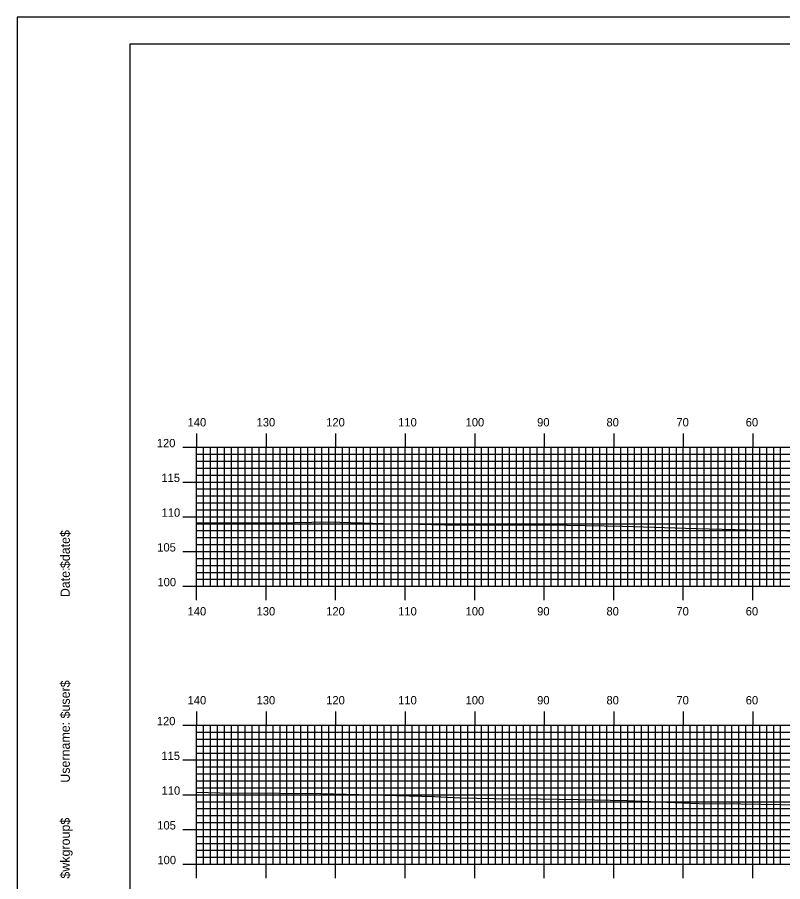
# Model space of a CAD drawing. Extents: x 1773203 to 1773546, y 442591 to 442811.
# Drawn here: x 1773202.8 to 1773312.9, y 442686.2 to 442810.5 of the extents above; entities that cross this region are included whole.
import ezdxf

# ---------------------------------------------------------------- set-up
doc = ezdxf.new("R2010")
doc.units = 0
for name, color, linetype in [('BORDER', 7, 'Continuous'), ('H_V ANNOTATION', 7, 'Continuous'), ('MAJOR', 7, 'Continuous'), ('MINOR', 7, 'Continuous'), ('PLOT BOUNDARY', 7, 'Continuous'), ('S_Roadway_Centerline', 7, 'Continuous')]:
    doc.layers.add(name, color=color, linetype=linetype)

msp = doc.modelspace()

# ---------------------------------------------------------------- linework, layer by layer
at = {"layer": 'BORDER'}
msp.add_lwpolyline([(1773219.03, 442596.67), (1773539.03, 442596.67), (1773539.03, 442806.67), (1773219.03, 442806.67)], close=True, dxfattribs=at)
at = {"layer": 'MAJOR'}
for p, q in [((1773228.63, 442750.67), (1773228.63, 442748.67)), ((1773238.63, 442750.67), (1773238.63, 442748.67)), ((1773248.63, 442750.67), (1773248.63, 442748.67)), ((1773258.63, 442750.67), (1773258.63, 442748.67)), ((1773268.63, 442750.67), (1773268.63, 442748.67)), ((1773278.63, 442750.67), (1773278.63, 442748.67)), ((1773288.63, 442750.67), (1773288.63, 442748.67)), ((1773298.63, 442750.67), (1773298.63, 442748.67)), ((1773308.63, 442750.67), (1773308.63, 442748.67)), ((1773226.63, 442748.67), (1773228.63, 442748.67)), ((1773228.63, 442748.67), (1773508.63, 442748.67)), ((1773228.63, 442728.67), (1773228.63, 442748.67)), ((1773228.63, 442728.67), (1773228.63, 442748.67)), ((1773228.63, 442748.67), (1773508.63, 442748.67)), ((1773238.63, 442728.67), (1773238.63, 442748.67)), ((1773248.63, 442728.67), (1773248.63, 442748.67)), ((1773258.63, 442728.67), (1773258.63, 442748.67)), ((1773268.63, 442728.67), (1773268.63, 442748.67)), ((1773278.63, 442728.67), (1773278.63, 442748.67)), ((1773288.63, 442728.67), (1773288.63, 442748.67)), ((1773298.63, 442728.67), (1773298.63, 442748.67)), ((1773308.63, 442728.67), (1773308.63, 442748.67)), ((1773226.63, 442743.67), (1773228.63, 442743.67)), ((1773228.63, 442743.67), (1773508.63, 442743.67)), ((1773226.63, 442738.67), (1773228.63, 442738.67)), ((1773228.63, 442738.67), (1773508.63, 442738.67)), ((1773226.63, 442733.67), (1773228.63, 442733.67)), ((1773228.63, 442733.67), (1773508.63, 442733.67)), ((1773226.63, 442728.67), (1773228.63, 442728.67)), ((1773228.63, 442728.67), (1773508.63, 442728.67)), ((1773228.63, 442728.67), (1773508.63, 442728.67)), ((1773228.63, 442726.66), (1773228.63, 442728.67)), ((1773238.63, 442726.66), (1773238.63, 442728.67)), ((1773248.63, 442726.66), (1773248.63, 442728.67)), ((1773258.63, 442726.66), (1773258.63, 442728.67)), ((1773268.63, 442726.66), (1773268.63, 442728.67)), ((1773278.63, 442726.66), (1773278.63, 442728.67)), ((1773288.63, 442726.66), (1773288.63, 442728.67)), ((1773298.63, 442726.66), (1773298.63, 442728.67)), ((1773308.63, 442726.66), (1773308.63, 442728.67)), ((1773228.63, 442710.67), (1773228.63, 442708.67)), ((1773238.63, 442710.67), (1773238.63, 442708.67)), ((1773248.63, 442710.67), (1773248.63, 442708.67)), ((1773258.63, 442710.67), (1773258.63, 442708.67)), ((1773268.63, 442710.67), (1773268.63, 442708.67)), ((1773278.63, 442710.67), (1773278.63, 442708.67)), ((1773288.63, 442710.67), (1773288.63, 442708.67)), ((1773298.63, 442710.67), (1773298.63, 442708.67)), ((1773308.63, 442710.67), (1773308.63, 442708.67)), ((1773226.63, 442708.67), (1773228.63, 442708.67)), ((1773228.63, 442708.67), (1773508.63, 442708.67)), ((1773228.63, 442688.67), (1773228.63, 442708.67)), ((1773228.63, 442688.67), (1773228.63, 442708.67)), ((1773228.63, 442708.67), (1773508.63, 442708.67)), ((1773238.63, 442688.67), (1773238.63, 442708.67)), ((1773248.63, 442688.67), (1773248.63, 442708.67)), ((1773258.63, 442688.67), (1773258.63, 442708.67)), ((1773268.63, 442688.67), (1773268.63, 442708.67)), ((1773278.63, 442688.67), (1773278.63, 442708.67)), ((1773288.63, 442688.67), (1773288.63, 442708.67)), ((1773298.63, 442688.67), (1773298.63, 442708.67)), ((1773308.63, 442688.67), (1773308.63, 442708.67)), ((1773226.63, 442703.67), (1773228.63, 442703.67)), ((1773228.63, 442703.67), (1773508.63, 442703.67)), ((1773226.63, 442698.67), (1773228.63, 442698.67)), ((1773228.63, 442698.67), (1773508.63, 442698.67)), ((1773226.63, 442693.67), (1773228.63, 442693.67)), ((1773228.63, 442693.67), (1773508.63, 442693.67)), ((1773226.63, 442688.67), (1773228.63, 442688.67)), ((1773228.63, 442688.67), (1773508.63, 442688.67)), ((1773228.63, 442688.67), (1773508.63, 442688.67)), ((1773228.63, 442686.66), (1773228.63, 442688.67)), ((1773238.63, 442686.66), (1773238.63, 442688.67)), ((1773248.63, 442686.66), (1773248.63, 442688.67)), ((1773258.63, 442686.66), (1773258.63, 442688.67)), ((1773268.63, 442686.66), (1773268.63, 442688.67)), ((1773278.63, 442686.66), (1773278.63, 442688.67)), ((1773288.63, 442686.66), (1773288.63, 442688.67)), ((1773298.63, 442686.66), (1773298.63, 442688.67)), ((1773308.63, 442686.66), (1773308.63, 442688.67))]:
    msp.add_line(p, q, dxfattribs=at)
at = {"layer": 'MINOR'}
for p, q in [((1773229.63, 442728.67), (1773229.63, 442748.67)), ((1773230.63, 442728.67), (1773230.63, 442748.67)), ((1773231.63, 442728.67), (1773231.63, 442748.67)), ((1773232.63, 442728.67), (1773232.63, 442748.67)), ((1773233.63, 442728.67), (1773233.63, 442748.67)), ((1773234.63, 442728.67), (1773234.63, 442748.67)), ((1773235.63, 442728.67), (1773235.63, 442748.67)), ((1773236.63, 442728.67), (1773236.63, 442748.67)), ((1773237.63, 442728.67), (1773237.63, 442748.67)), ((1773239.63, 442728.67), (1773239.63, 442748.67)), ((1773240.63, 442728.67), (1773240.63, 442748.67)), ((1773241.63, 442728.67), (1773241.63, 442748.67)), ((1773242.63, 442728.67), (1773242.63, 442748.67)), ((1773243.63, 442728.67), (1773243.63, 442748.67)), ((1773244.63, 442728.67), (1773244.63, 442748.67)), ((1773245.63, 442728.67), (1773245.63, 442748.67)), ((1773246.63, 442728.67), (1773246.63, 442748.67)), ((1773247.63, 442728.67), (1773247.63, 442748.67)), ((1773249.63, 442728.67), (1773249.63, 442748.67)), ((1773250.63, 442728.67), (1773250.63, 442748.67)), ((1773251.63, 442728.67), (1773251.63, 442748.67)), ((1773252.63, 442728.67), (1773252.63, 442748.67)), ((1773253.63, 442728.67), (1773253.63, 442748.67)), ((1773254.63, 442728.67), (1773254.63, 442748.67)), ((1773255.63, 442728.67), (1773255.63, 442748.67)), ((1773256.63, 442728.67), (1773256.63, 442748.67)), ((1773257.63, 442728.67), (1773257.63, 442748.67)), ((1773259.63, 442728.67), (1773259.63, 442748.67)), ((1773260.63, 442728.67), (1773260.63, 442748.67)), ((1773261.63, 442728.67), (1773261.63, 442748.67)), ((1773262.63, 442728.67), (1773262.63, 442748.67)), ((1773263.63, 442728.67), (1773263.63, 442748.67)), ((1773264.63, 442728.67), (1773264.63, 442748.67)), ((1773265.63, 442728.67), (1773265.63, 442748.67)), ((1773266.63, 442728.67), (1773266.63, 442748.67)), ((1773267.63, 442728.67), (1773267.63, 442748.67)), ((1773269.63, 442728.67), (1773269.63, 442748.67)), ((1773270.63, 442728.67), (1773270.63, 442748.67)), ((1773271.63, 442728.67), (1773271.63, 442748.67)), ((1773272.63, 442728.67), (1773272.63, 442748.67)), ((1773273.63, 442728.67), (1773273.63, 442748.67)), ((1773274.63, 442728.67), (1773274.63, 442748.67)), ((1773275.63, 442728.67), (1773275.63, 442748.67)), ((1773276.63, 442728.67), (1773276.63, 442748.67)), ((1773277.63, 442728.67), (1773277.63, 442748.67)), ((1773279.63, 442728.67), (1773279.63, 442748.67)), ((1773280.63, 442728.67), (1773280.63, 442748.67)), ((1773281.63, 442728.67), (1773281.63, 442748.67)), ((1773282.63, 442728.67), (1773282.63, 442748.67)), ((1773283.63, 442728.67), (1773283.63, 442748.67)), ((1773284.63, 442728.67), (1773284.63, 442748.67)), ((1773285.63, 442728.67), (1773285.63, 442748.67)), ((1773286.63, 442728.67), (1773286.63, 442748.67)), ((1773287.63, 442728.67), (1773287.63, 442748.67)), ((1773289.63, 442728.67), (1773289.63, 442748.67)), ((1773290.63, 442728.67), (1773290.63, 442748.67)), ((1773291.63, 442728.67), (1773291.63, 442748.67)), ((1773292.63, 442728.67), (1773292.63, 442748.67)), ((1773293.63, 442728.67), (1773293.63, 442748.67)), ((1773294.63, 442728.67), (1773294.63, 442748.67)), ((1773295.63, 442728.67), (1773295.63, 442748.67)), ((1773296.63, 442728.67), (1773296.63, 442748.67)), ((1773297.63, 442728.67), (1773297.63, 442748.67)), ((1773299.63, 442728.67), (1773299.63, 442748.67)), ((1773300.63, 442728.67), (1773300.63, 442748.67)), ((1773301.63, 442728.67), (1773301.63, 442748.67)), ((1773302.63, 442728.67), (1773302.63, 442748.67)), ((1773303.63, 442728.67), (1773303.63, 442748.67)), ((1773304.63, 442728.67), (1773304.63, 442748.67)), ((1773305.63, 442728.67), (1773305.63, 442748.67)), ((1773306.63, 442728.67), (1773306.63, 442748.67)), ((1773307.63, 442728.67), (1773307.63, 442748.67)), ((1773309.63, 442728.67), (1773309.63, 442748.67)), ((1773310.63, 442728.67), (1773310.63, 442748.67)), ((1773311.63, 442728.67), (1773311.63, 442748.67)), ((1773312.63, 442728.67), (1773312.63, 442748.67)), ((1773228.63, 442747.67), (1773508.63, 442747.67)), ((1773228.63, 442747.67), (1773230.64, 442747.67)), ((1773228.63, 442746.67), (1773508.63, 442746.67)), ((1773228.63, 442746.67), (1773230.64, 442746.67)), ((1773228.63, 442745.67), (1773508.63, 442745.67)), ((1773228.63, 442745.67), (1773230.64, 442745.67)), ((1773228.63, 442744.67), (1773508.63, 442744.67)), ((1773228.63, 442744.67), (1773230.64, 442744.67)), ((1773228.63, 442742.67), (1773508.63, 442742.67)), ((1773228.63, 442742.67), (1773230.64, 442742.67)), ((1773228.63, 442741.67), (1773508.63, 442741.67)), ((1773228.63, 442741.67), (1773230.64, 442741.67)), ((1773228.63, 442740.67), (1773508.63, 442740.67)), ((1773228.63, 442740.67), (1773230.64, 442740.67)), ((1773228.63, 442739.67), (1773508.63, 442739.67)), ((1773228.63, 442739.67), (1773230.64, 442739.67)), ((1773228.63, 442737.67), (1773508.63, 442737.67)), ((1773228.63, 442737.67), (1773230.64, 442737.67)), ((1773228.63, 442736.67), (1773508.63, 442736.67)), ((1773228.63, 442736.67), (1773230.64, 442736.67)), ((1773228.63, 442735.67), (1773508.63, 442735.67)), ((1773228.63, 442735.67), (1773230.64, 442735.67)), ((1773228.63, 442734.67), (1773508.63, 442734.67)), ((1773228.63, 442734.67), (1773230.64, 442734.67)), ((1773228.63, 442732.67), (1773508.63, 442732.67)), ((1773228.63, 442732.67), (1773230.64, 442732.67)), ((1773228.63, 442731.67), (1773508.63, 442731.67)), ((1773228.63, 442731.67), (1773230.64, 442731.67)), ((1773228.63, 442730.67), (1773508.63, 442730.67)), ((1773228.63, 442730.67), (1773230.64, 442730.67)), ((1773228.63, 442729.67), (1773508.63, 442729.67)), ((1773228.63, 442729.67), (1773230.64, 442729.67)), ((1773229.63, 442688.67), (1773229.63, 442708.67)), ((1773230.63, 442688.67), (1773230.63, 442708.67)), ((1773231.63, 442688.67), (1773231.63, 442708.67)), ((1773232.63, 442688.67), (1773232.63, 442708.67)), ((1773233.63, 442688.67), (1773233.63, 442708.67)), ((1773234.63, 442688.67), (1773234.63, 442708.67)), ((1773235.63, 442688.67), (1773235.63, 442708.67)), ((1773236.63, 442688.67), (1773236.63, 442708.67)), ((1773237.63, 442688.67), (1773237.63, 442708.67)), ((1773239.63, 442688.67), (1773239.63, 442708.67)), ((1773240.63, 442688.67), (1773240.63, 442708.67)), ((1773241.63, 442688.67), (1773241.63, 442708.67)), ((1773242.63, 442688.67), (1773242.63, 442708.67)), ((1773243.63, 442688.67), (1773243.63, 442708.67)), ((1773244.63, 442688.67), (1773244.63, 442708.67)), ((1773245.63, 442688.67), (1773245.63, 442708.67)), ((1773246.63, 442688.67), (1773246.63, 442708.67)), ((1773247.63, 442688.67), (1773247.63, 442708.67)), ((1773249.63, 442688.67), (1773249.63, 442708.67)), ((1773250.63, 442688.67), (1773250.63, 442708.67)), ((1773251.63, 442688.67), (1773251.63, 442708.67)), ((1773252.63, 442688.67), (1773252.63, 442708.67)), ((1773253.63, 442688.67), (1773253.63, 442708.67)), ((1773254.63, 442688.67), (1773254.63, 442708.67)), ((1773255.63, 442688.67), (1773255.63, 442708.67)), ((1773256.63, 442688.67), (1773256.63, 442708.67)), ((1773257.63, 442688.67), (1773257.63, 442708.67)), ((1773259.63, 442688.67), (1773259.63, 442708.67)), ((1773260.63, 442688.67), (1773260.63, 442708.67)), ((1773261.63, 442688.67), (1773261.63, 442708.67)), ((1773262.63, 442688.67), (1773262.63, 442708.67)), ((1773263.63, 442688.67), (1773263.63, 442708.67)), ((1773264.63, 442688.67), (1773264.63, 442708.67)), ((1773265.63, 442688.67), (1773265.63, 442708.67)), ((1773266.63, 442688.67), (1773266.63, 442708.67)), ((1773267.63, 442688.67), (1773267.63, 442708.67)), ((1773269.63, 442688.67), (1773269.63, 442708.67)), ((1773270.63, 442688.67), (1773270.63, 442708.67)), ((1773271.63, 442688.67), (1773271.63, 442708.67)), ((1773272.63, 442688.67), (1773272.63, 442708.67)), ((1773273.63, 442688.67), (1773273.63, 442708.67)), ((1773274.63, 442688.67), (1773274.63, 442708.67)), ((1773275.63, 442688.67), (1773275.63, 442708.67)), ((1773276.63, 442688.67), (1773276.63, 442708.67)), ((1773277.63, 442688.67), (1773277.63, 442708.67)), ((1773279.63, 442688.67), (1773279.63, 442708.67)), ((1773280.63, 442688.67), (1773280.63, 442708.67)), ((1773281.63, 442688.67), (1773281.63, 442708.67)), ((1773282.63, 442688.67), (1773282.63, 442708.67)), ((1773283.63, 442688.67), (1773283.63, 442708.67)), ((1773284.63, 442688.67), (1773284.63, 442708.67)), ((1773285.63, 442688.67), (1773285.63, 442708.67)), ((1773286.63, 442688.67), (1773286.63, 442708.67)), ((1773287.63, 442688.67), (1773287.63, 442708.67)), ((1773289.63, 442688.67), (1773289.63, 442708.67)), ((1773290.63, 442688.67), (1773290.63, 442708.67)), ((1773291.63, 442688.67), (1773291.63, 442708.67)), ((1773292.63, 442688.67), (1773292.63, 442708.67)), ((1773293.63, 442688.67), (1773293.63, 442708.67)), ((1773294.63, 442688.67), (1773294.63, 442708.67)), ((1773295.63, 442688.67), (1773295.63, 442708.67)), ((1773296.63, 442688.67), (1773296.63, 442708.67)), ((1773297.63, 442688.67), (1773297.63, 442708.67)), ((1773299.63, 442688.67), (1773299.63, 442708.67)), ((1773300.63, 442688.67), (1773300.63, 442708.67)), ((1773301.63, 442688.67), (1773301.63, 442708.67)), ((1773302.63, 442688.67), (1773302.63, 442708.67)), ((1773303.63, 442688.67), (1773303.63, 442708.67)), ((1773304.63, 442688.67), (1773304.63, 442708.67)), ((1773305.63, 442688.67), (1773305.63, 442708.67)), ((1773306.63, 442688.67), (1773306.63, 442708.67)), ((1773307.63, 442688.67), (1773307.63, 442708.67)), ((1773309.63, 442688.67), (1773309.63, 442708.67)), ((1773310.63, 442688.67), (1773310.63, 442708.67)), ((1773311.63, 442688.67), (1773311.63, 442708.67)), ((1773312.63, 442688.67), (1773312.63, 442708.67)), ((1773228.63, 442707.67), (1773508.63, 442707.67)), ((1773228.63, 442707.67), (1773230.64, 442707.67)), ((1773228.63, 442706.67), (1773508.63, 442706.67)), ((1773228.63, 442706.67), (1773230.64, 442706.67)), ((1773228.63, 442705.67), (1773508.63, 442705.67)), ((1773228.63, 442705.67), (1773230.64, 442705.67)), ((1773228.63, 442704.67), (1773508.63, 442704.67)), ((1773228.63, 442704.67), (1773230.64, 442704.67)), ((1773228.63, 442702.67), (1773508.63, 442702.67)), ((1773228.63, 442702.67), (1773230.64, 442702.67)), ((1773228.63, 442701.67), (1773508.63, 442701.67)), ((1773228.63, 442701.67), (1773230.64, 442701.67)), ((1773228.63, 442700.67), (1773508.63, 442700.67)), ((1773228.63, 442700.67), (1773230.64, 442700.67)), ((1773228.63, 442699.67), (1773508.63, 442699.67)), ((1773228.63, 442699.67), (1773230.64, 442699.67)), ((1773228.63, 442697.67), (1773508.63, 442697.67)), ((1773228.63, 442697.67), (1773230.64, 442697.67)), ((1773228.63, 442696.67), (1773508.63, 442696.67)), ((1773228.63, 442696.67), (1773230.64, 442696.67)), ((1773228.63, 442695.67), (1773508.63, 442695.67)), ((1773228.63, 442695.67), (1773230.64, 442695.67)), ((1773228.63, 442694.67), (1773508.63, 442694.67)), ((1773228.63, 442694.67), (1773230.64, 442694.67)), ((1773228.63, 442692.67), (1773508.63, 442692.67)), ((1773228.63, 442692.67), (1773230.64, 442692.67)), ((1773228.63, 442691.67), (1773508.63, 442691.67)), ((1773228.63, 442691.67), (1773230.64, 442691.67)), ((1773228.63, 442690.67), (1773508.63, 442690.67)), ((1773228.63, 442690.67), (1773230.64, 442690.67)), ((1773228.63, 442689.67), (1773508.63, 442689.67)), ((1773228.63, 442689.67), (1773230.64, 442689.67))]:
    msp.add_line(p, q, dxfattribs=at)
at = {"layer": 'PLOT BOUNDARY'}
msp.add_lwpolyline([(1773202.85, 442590.55), (1773542.85, 442590.55), (1773542.85, 442810.55), (1773202.85, 442810.55)], close=True, dxfattribs=at)
at = {"layer": 'S_Roadway_Centerline'}
for points in [[(1773228.63, 442737.81), (1773229.19, 442737.79), (1773240.26, 442737.8), (1773247.67, 442737.93), (1773257.14, 442737.66), (1773260.51, 442737.6), (1773264.32, 442737.5), (1773272.4, 442737.47), (1773279.3, 442737.53), (1773289.89, 442737.32), (1773300.46, 442736.97), (1773315.37, 442736.59)], [(1773228.63, 442699.05), (1773231.96, 442698.94), (1773240.72, 442698.89), (1773246.48, 442698.86), (1773262.87, 442698.4), (1773266.47, 442698.23), (1773271.38, 442698.13), (1773278.06, 442698.08), (1773283.5, 442697.98), (1773290.51, 442697.86), (1773300.87, 442697.41), (1773306.91, 442697.34), (1773315.63, 442697.23)]]:
    msp.add_lwpolyline(points, dxfattribs=at)

# ---------------------------------------------------------------- texts
at = {"layer": 'BORDER'}
for s, p in [('$date$', (1773210.4, 442731.28)), ('Date:', (1773210.4, 442727.1)), ('$user$', (1773210.4, 442709.65)), ('Username:', (1773210.4, 442700.4)), ('$wkgroup$', (1773210.4, 442686.6))]:
    msp.add_text(s, height=1.339, rotation=90, dxfattribs=at).set_placement(p)
at = {"layer": 'H_V ANNOTATION'}
for s, p in [('140', (1773227.34, 442751.67)), ('130', (1773237.26, 442751.67)), ('120', (1773247.27, 442751.67)), ('110', (1773257.62, 442751.67)), ('100', (1773267.32, 442751.67)), ('90', (1773277.61, 442751.67)), ('80', (1773287.58, 442751.67)), ('70', (1773297.64, 442751.67)), ('60', (1773307.61, 442751.67)), ('120', (1773222.91, 442748.67)), ('115', (1773223.57, 442743.67)), ('110', (1773223.6, 442738.67)), ('105', (1773222.97, 442733.67)), ('100', (1773223, 442728.67)), ('140', (1773227.34, 442724.47)), ('130', (1773237.26, 442724.47)), ('120', (1773247.27, 442724.47)), ('110', (1773257.62, 442724.47)), ('100', (1773267.32, 442724.47)), ('90', (1773277.61, 442724.47)), ('80', (1773287.58, 442724.47)), ('70', (1773297.64, 442724.47)), ('60', (1773307.61, 442724.47)), ('140', (1773227.34, 442711.67)), ('130', (1773237.26, 442711.67)), ('120', (1773247.27, 442711.67)), ('110', (1773257.62, 442711.67)), ('100', (1773267.32, 442711.67)), ('90', (1773277.61, 442711.67)), ('80', (1773287.58, 442711.67)), ('70', (1773297.64, 442711.67)), ('60', (1773307.61, 442711.67)), ('120', (1773222.91, 442708.67)), ('115', (1773223.57, 442703.67)), ('110', (1773223.6, 442698.67)), ('105', (1773222.97, 442693.67)), ('100', (1773223, 442688.67))]:
    msp.add_text(s, height=1.2, dxfattribs=at).set_placement(p)
at = {"layer": 'MAJOR'}
for p in [(1773228.62, 442728.67), (1773228.62, 442688.67)]:
    msp.add_text('-', height=0.012, dxfattribs=at).set_placement(p)

doc.saveas('drawing.dxf')
